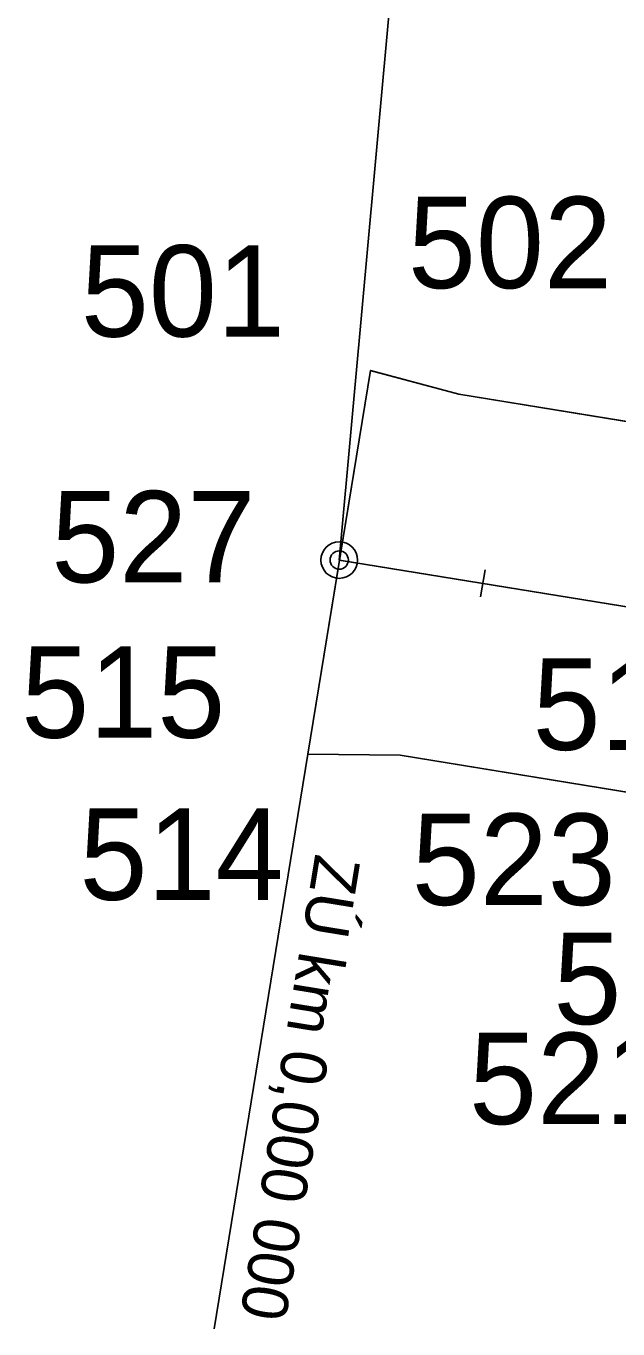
# Model space of a CAD drawing. Extents: x -743186.9 to -743133.1, y -1127113.3 to -1127042.8.
# Drawn here: x -743185.92 to -743179.45, y -1127104.86 to -1127090.61 of the extents above; entities that cross this region are included whole.
import ezdxf

# ---------------------------------------------------------------- set-up
doc = ezdxf.new("R2010")
doc.units = 0
for name, color, linetype in [('bublina_fialová_čára_tenká', 7, 'Continuous'), ('KOMUNIKACE_KRAJNICE', 7, 'Continuous'), ('křížek', 7, 'Continuous'), ('OSA_KOMUNIKACE', 7, 'Continuous'), ('OSA_POP', 7, 'Continuous'), ('SRAFA_UPRAVA', 7, 'Continuous'), ('Vrstva 60', 7, 'Continuous')]:
    doc.layers.add(name, color=color, linetype=linetype)

# ---------------------------------------------------------------- blocks, each defined once
blk = doc.blocks.new('AeccTickCircle')
blk.add_circle((0, 0), 0.5)
blk = doc.blocks.new('POINT_DISPLAY')
blk.add_line((0, 0), (0, 0))

msp = doc.modelspace()

# ---------------------------------------------------------------- linework, layer by layer
at = {"layer": 'bublina_fialová_čára_tenká'}
msp.add_line((-743179.562, -1127064.096), (-743182.5, -1127096.45), dxfattribs=at)
at = {"layer": 'KOMUNIKACE_KRAJNICE'}
for p, q in [((-743182.845, -1127098.574), (-743182.159, -1127094.376)), ((-743182.162, -1127094.375), (-743181.191, -1127094.636)), ((-743182.845, -1127098.574), (-743181.834, -1127098.584))]:
    msp.add_line(p, q, dxfattribs=at)
for points in [[(-743175.856, -1127095.505), (-743181.191, -1127094.636)], [(-743178.176, -1127099.18), (-743181.834, -1127098.584)]]:
    msp.add_lwpolyline(points, dxfattribs=at)
at = {"layer": 'OSA_KOMUNIKACE'}
msp.add_line((-743164.284, -1127099.415), (-743182.5, -1127096.45), dxfattribs=at)
at = {"layer": 'OSA_POP'}
for p, q in [((-743180.954, -1127096.853), (-743180.906, -1127096.557)), ((-743182.845, -1127098.574), (-743183.869, -1127104.859))]:
    msp.add_line(p, q, dxfattribs=at)
at = {"layer": 'SRAFA_UPRAVA'}
for p, q in [((-743182.159, -1127094.376), (-743182.498, -1127096.45)), ((-743181.191, -1127094.636), (-743182.159, -1127094.376)), ((-743175.856, -1127095.505), (-743181.191, -1127094.636)), ((-743182.498, -1127096.45), (-743182.845, -1127098.574)), ((-743182.498, -1127096.45), (-743177.016, -1127097.342)), ((-743177.016, -1127097.342), (-743182.498, -1127096.45)), ((-743182.845, -1127098.574), (-743181.834, -1127098.584)), ((-743181.834, -1127098.584), (-743178.176, -1127099.18))]:
    msp.add_line(p, q, dxfattribs=at)
at = {"layer": 'Vrstva 60'}
for p, q in [((-743182.159, -1127094.376), (-743182.159, -1127094.376)), ((-743181.191, -1127094.636), (-743181.191, -1127094.636)), ((-743182.5, -1127096.45), (-743182.5, -1127096.45)), ((-743182.846, -1127098.574), (-743182.846, -1127098.574)), ((-743181.834, -1127098.584), (-743181.834, -1127098.584))]:
    msp.add_line(p, q, dxfattribs=at)

# ---------------------------------------------------------------- block references
at = {"layer": 'křížek', "xscale": 10, "yscale": 10, "rotation": 61.14491455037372}
for p in [(-743182.159, -1127094.376), (-743181.191, -1127094.636), (-743182.5, -1127096.45), (-743182.846, -1127098.574), (-743181.834, -1127098.584)]:
    msp.add_blockref('POINT_DISPLAY', p, dxfattribs=at)
at = {"layer": 'OSA_POP', "rotation": -9.247996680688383}
for xscale, yscale in [(0.4, 0.39999999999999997), (0.2, 0.19999999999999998)]:
    msp.add_blockref('AeccTickCircle', (-743182.5, -1127096.45), dxfattribs=dict(at, xscale=xscale, yscale=yscale))

# ---------------------------------------------------------------- texts
at = {"layer": 'OSA_POP'}
msp.add_text('ZÚ km 0,000 000', height=0.5, rotation=260.752, dxfattribs=at).set_placement((-743182.76, -1127099.653))
at = {"layer": 'Vrstva 60'}
for s, p in [('502', (-743181.749, -1127093.476)), ('501', (-743185.325, -1127094.006)), ('527', (-743185.648, -1127096.694)), ('515', (-743185.977, -1127098.393)), ('513', (-743180.386, -1127098.526)), ('514', (-743185.34, -1127100.166)), ('523', (-743181.707, -1127100.222)), ('512', (-743180.159, -1127101.526)), ('521', (-743181.081, -1127102.619))]:
    msp.add_text(s, height=1, dxfattribs=at).set_placement(p)

doc.saveas('drawing.dxf')
